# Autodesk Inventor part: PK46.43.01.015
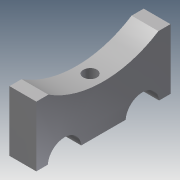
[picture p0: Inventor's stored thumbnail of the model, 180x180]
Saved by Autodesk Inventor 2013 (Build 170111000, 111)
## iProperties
Shininess: 64.0
Length Units: 11269
Angle Units: 11279
Time Units: 11290
Mass Units: 11283
Length Display Precision: 3
Angle Display Precision: 2
Compacted: True
Part Number: PK46.43.01.015
Document SubType Name: Modeling
Created: 2004-12
Material: Steel, High Strength Low Alloy
Designer: ELarisa
Manufacturer: Standard
Standards Organization: Custom
Density: 7.84 g/cm^3
Density: 0.0
Volumn: 0.0
Area: 0.0
PropertySet Name: Model Information
Control State: 0
Master: False
Checked Out: False
Checked Out Date: 2008-10-09
Last Check In Date: 2008-10-09
Author: ELarisa
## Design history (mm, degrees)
sketch "Эскиз3"
  geometry: L1 (-52.305, -27.794)-(-52.305, -72.794); L2 (47.695, -72.794)-(47.695, -27.794); L3 (47.695, -27.794)-(38.682, -27.794); L4 (-43.293, -27.794)-(-52.305, -27.794); L5 (-52.305, -72.794)-(-43.765, -72.794); L6 (-18.846, -72.794)-(14.235, -72.794); L7 (39.154, -72.794)-(47.695, -72.794); A1 r 76 centre (-2.305, 36.206) between (-43.293, -27.794) and (38.682, -27.794); A2 r 12.5 centre (-31.305, -73.794) between (-18.846, -72.794) and (-43.765, -72.794); A3 r 12.5 centre (26.695, -73.794) between (39.154, -72.794) and (14.235, -72.794)
  constraints: 14 end point, 7 parallel, 6 point on circle, 3 centre point, 3 perpendicular, 2 collinear, 1 vertical
  dimensions: "d24" = 45 distance of L1.start L1.end; "d25" = 76 radius of A1; "d26" = 109 distance from line of L6 A1.centre; "d27" = 45 distance of L2.start L2.end; "d28" = 1 distance from line of A2.centre L5; "d29" = 1 distance from line of L7 A3.centre; "d30" = 50 distance from line of A1.centre L1; "d31" = 58 distance of A3.centre A2.centre; "d32" = 12.5 radius of A2; "d33" = 12.5 radius of A3; "d34" = 100 distance between parallel lines of L2 L1; "d35" = 21 distance from line of A2.centre L1
extrude "Выдавливание3" new body sketch "Эскиз3" distance "d36" = 20; taper "d37" = 0 deg
sketch "Эскиз4"
  geometry: L1 (-20, 33.08)-(-20, 0) reference; L2 (0, -33.46)-(-20, -33.46) reference; 1 further point
  dimensions: "d39" = 50 distance from line of point (-10, 16.54) L2; "d40" = 10 distance from line of point (-10, 16.54) L1
hole "Отверстие1" sketch "Эскиз4" diameter "d41" = 10.106; stored, may be unused: countersink angle "d45" = 90 deg, drill point angle "d47" = 118 deg; dims "d42" = 26, "d43" = 15.2, "d44" = 2, "d46" = 26
body "Solid1"
other parameters: "d9" = 34, "d10" = 34
